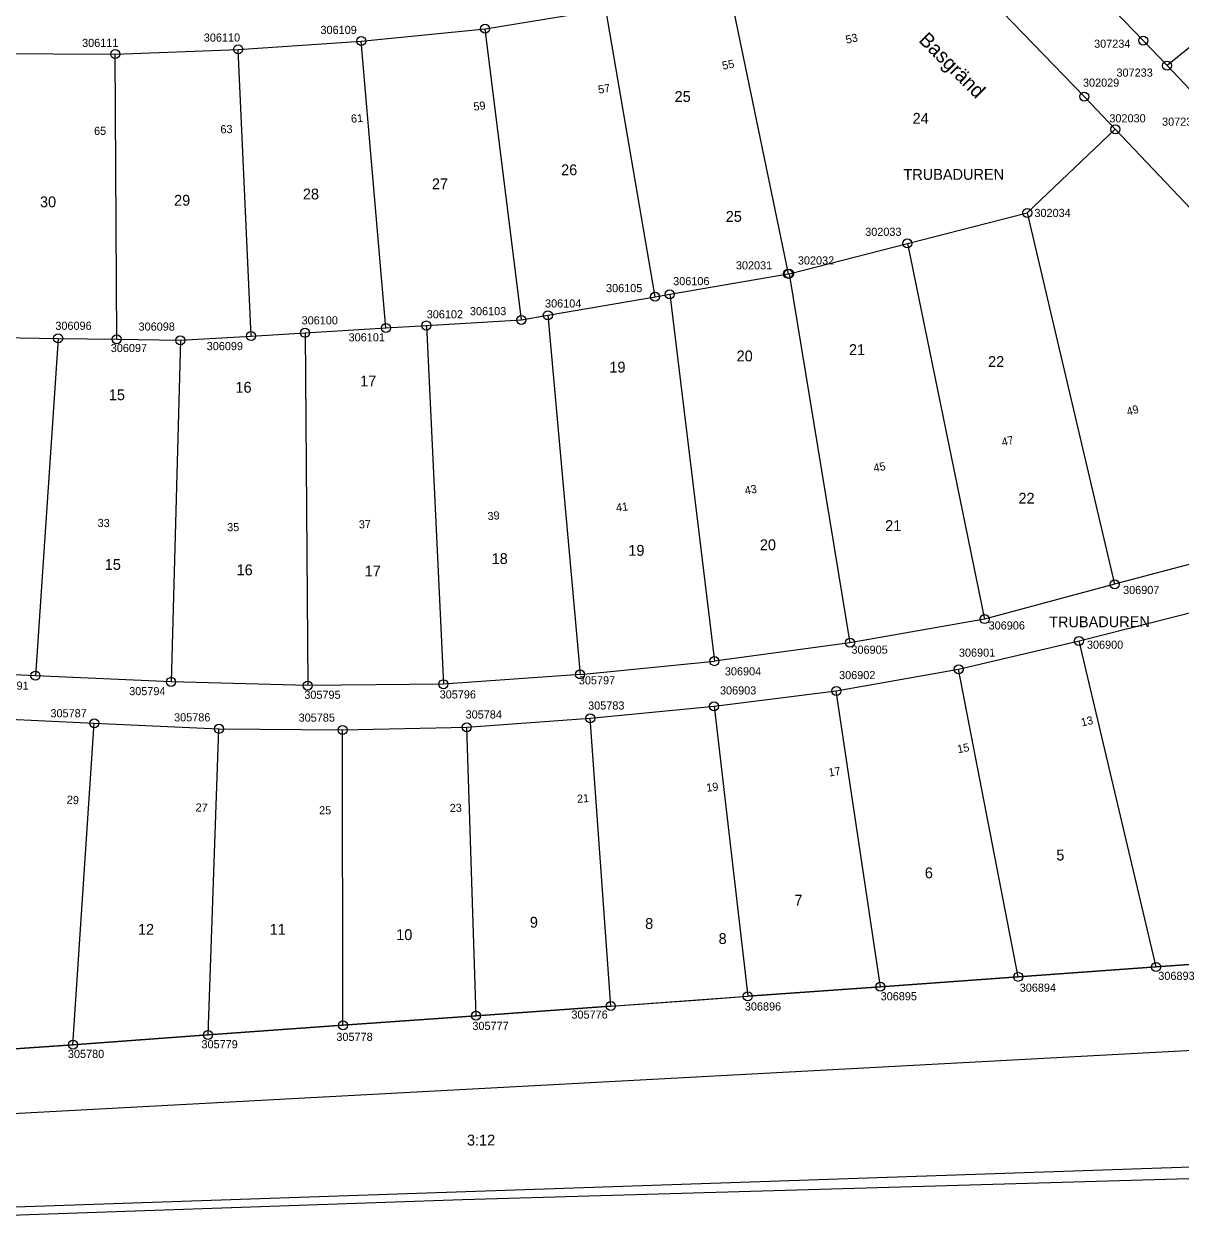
# Model space of a CAD drawing. Extents: x 141995 to 152570, y 6580184 to 6586000.
# Drawn here: x 142151.4 to 142279.5, y 6585356 to 6585489.3 of the extents above; entities that cross this region are included whole.
import ezdxf

# ---------------------------------------------------------------- set-up
doc = ezdxf.new("R2010")
doc.units = 0
for name, color, linetype in [('Level 10', 7, 'Continuous'), ('Level 13', 7, 'Continuous'), ('Level 43', 7, 'Continuous'), ('Level 5', 7, 'Continuous'), ('Level 51', 7, 'Continuous'), ('Level 53', 7, 'Continuous'), ('Level 54', 7, 'Continuous'), ('Level 58', 7, 'Continuous'), ('Level 59', 7, 'Continuous'), ('Level 6', 7, 'Continuous'), ('Level 7', 7, 'Continuous')]:
    doc.layers.add(name, color=color, linetype=linetype)

msp = doc.modelspace()

# ---------------------------------------------------------------- linework, layer by layer
at = {"layer": 'Level 10'}
for centre in [(142202.46, 6585488.79), (142188.75, 6585487.43), (142275.29, 6585487.49), (142175.13, 6585486.51), (142161.52, 6585485.99), (142277.92, 6585484.71), (142268.76, 6585481.29), (142272.2, 6585477.67), (142262.45, 6585468.41), (142249.19, 6585465.03), (142235.99, 6585461.67), (142236.09, 6585461.68), (142222.89, 6585459.41), (142221.27, 6585459.13), (142209.4, 6585457.08), (142191.48, 6585455.68), (142195.96, 6585455.95), (142206.47, 6585456.57), (142155.21, 6585454.53), (142161.69, 6585454.43), (142168.74, 6585454.31), (142176.56, 6585454.78), (142182.53, 6585455.14), (142272.12, 6585427.31), (142257.73, 6585423.45), (142242.83, 6585420.84), (142268.19, 6585421.04), (142227.84, 6585418.8), (142152.7, 6585417.19), (142212.97, 6585417.33), (142254.86, 6585417.91), (142167.71, 6585416.51), (142182.83, 6585416.1), (142197.85, 6585416.25), (142241.32, 6585415.5), (142227.79, 6585413.8), (142159.2, 6585411.93), (142200.43, 6585411.49), (142214.09, 6585412.48), (142173, 6585411.31), (142186.68, 6585411.19), (142276.72, 6585384.95), (142261.45, 6585383.86), (142246.2, 6585382.76), (142231.53, 6585381.71), (142201.46, 6585379.55), (142216.37, 6585380.62), (142186.73, 6585378.5), (142171.8, 6585377.43), (142156.85, 6585376.35)]:
    msp.add_circle(centre, 0.5, dxfattribs=at)
at = {"layer": 'Level 13'}
msp.add_lwpolyline([(142106.18, 6585355.96), (142199.95, 6585359.22), (142280.34, 6585361.53), (142298.3, 6585362.96), (142308.55, 6585364.2), (142315.26, 6585364.94), (142322.71, 6585365.48), (142328.56, 6585365.72), (142332.32, 6585365.37), (142336.72, 6585364.61), (142340.97, 6585363.81), (142343.67, 6585363.75), (142345.72, 6585364.6), (142347.07, 6585365.5), (142347.87, 6585367.45), (142347.76, 6585371.19)], dxfattribs=at)
at = {"layer": 'Level 5'}
for points in [[(142275.29, 6585487.49), (142265.8, 6585497.34)], [(142257.48, 6585492.99), (142268.76, 6585481.29)], [(142277.92, 6585484.71), (142275.29, 6585487.49)], [(142282.99, 6585479.38), (142277.92, 6585484.71)], [(142268.76, 6585481.29), (142272.2, 6585477.67)], [(142272.2, 6585477.67), (142305.7, 6585442.37)], [(142291.9, 6585386.04), (142276.72, 6585384.95)], [(142276.72, 6585384.95), (142261.45, 6585383.86)], [(142246.2, 6585382.76), (142231.53, 6585381.71)], [(142261.45, 6585383.86), (142246.2, 6585382.76)], [(142216.37, 6585380.62), (142231.53, 6585381.71)], [(142216.37, 6585380.62), (142201.46, 6585379.55)], [(142201.46, 6585379.55), (142186.73, 6585378.5)], [(142171.8, 6585377.43), (142156.85, 6585376.35)], [(142186.73, 6585378.5), (142171.8, 6585377.43)], [(142156.85, 6585376.35), (142142.94, 6585375.36)], [(142143.25, 6585368.36), (142295.25, 6585376.5)], [(142094.06, 6585356.49), (142340.21, 6585364.86)]]:
    msp.add_lwpolyline(points, dxfattribs=at)
at = {"layer": 'Level 6'}
for points in [[(142161.78, 6585599.85), (142163.75, 6585595.96), (142164.09, 6585595.28), (142167.01, 6585591.08), (142170.49, 6585587.33), (142174.96, 6585583.19), (142180.35, 6585578.22), (142185.73, 6585573.24), (142195.5, 6585564.2), (142205.48, 6585554.98), (142211, 6585549.86), (142216.54, 6585544.75), (142222.07, 6585539.63), (142227.15, 6585534.94), (142228.61, 6585533.59), (142240.56, 6585522.35), (142252.33, 6585510.92), (142263.91, 6585499.3), (142265.8, 6585497.34), (142275.29, 6585487.49), (142277.92, 6585484.71), (142282.99, 6585479.38)], [(142268.76, 6585481.29), (142257.48, 6585492.99), (142253.2, 6585497.29), (142246, 6585504.51), (142242.37, 6585508.05), (142234.34, 6585515.84), (142226.12, 6585523.57), (142222.49, 6585526.97), (142203, 6585545), (142172.41, 6585573.3), (142164.38, 6585580.72), (142159.99, 6585585.41), (142156.32, 6585590.67), (142155.3, 6585592.5), (142154.06, 6585594.1), (142152.36, 6585595.2), (142150.39, 6585595.67)], [(142303.68, 6585444.5), (142272.2, 6585477.67), (142268.76, 6585481.29)], [(142142.94, 6585375.36), (142156.85, 6585376.35), (142171.8, 6585377.43), (142186.73, 6585378.5), (142201.46, 6585379.55), (142216.37, 6585380.62), (142226.24, 6585381.33), (142231.53, 6585381.71), (142246.2, 6585382.76), (142261.45, 6585383.86), (142276.72, 6585384.95), (142291.9, 6585386.04)]]:
    msp.add_lwpolyline(points, dxfattribs=at)
at = {"layer": 'Level 7'}
for points in [[(142306.32, 6585507.63), (142277.92, 6585484.71)], [(142229.37, 6585493.73), (142235.99, 6585461.67)], [(142202.46, 6585488.79), (142215.83, 6585490.98)], [(142221.27, 6585459.13), (142215.83, 6585490.98)], [(142188.75, 6585487.43), (142202.46, 6585488.79)], [(142206.47, 6585456.57), (142202.46, 6585488.79)], [(142175.13, 6585486.51), (142188.75, 6585487.43)], [(142191.48, 6585455.68), (142188.75, 6585487.43)], [(142147.81, 6585486.06), (142161.52, 6585485.99)], [(142161.52, 6585485.99), (142175.13, 6585486.51)], [(142161.69, 6585454.43), (142161.52, 6585485.99)], [(142176.56, 6585454.78), (142175.13, 6585486.51)], [(142262.45, 6585468.41), (142272.2, 6585477.67)], [(142249.19, 6585465.03), (142262.45, 6585468.41)], [(142262.45, 6585468.41), (142272.12, 6585427.31)], [(142236.09, 6585461.68), (142249.19, 6585465.03)], [(142249.19, 6585465.03), (142257.73, 6585423.45)], [(142222.89, 6585459.41), (142235.99, 6585461.67)], [(142235.99, 6585461.67), (142236.09, 6585461.68)], [(142236.09, 6585461.68), (142242.83, 6585420.84)], [(142209.4, 6585457.08), (142221.27, 6585459.13)], [(142221.27, 6585459.13), (142222.89, 6585459.41)], [(142222.89, 6585459.41), (142227.84, 6585418.8)], [(142191.48, 6585455.68), (142195.96, 6585455.95)], [(142195.96, 6585455.95), (142206.47, 6585456.57)], [(142195.96, 6585455.95), (142197.85, 6585416.25)], [(142206.47, 6585456.57), (142209.4, 6585457.08)], [(142209.4, 6585457.08), (142212.97, 6585417.33)], [(142146.73, 6585454.67), (142155.21, 6585454.53)], [(142168.74, 6585454.31), (142176.56, 6585454.78)], [(142176.56, 6585454.78), (142182.53, 6585455.14)], [(142182.53, 6585455.14), (142191.48, 6585455.68)], [(142182.53, 6585455.14), (142182.83, 6585416.1)], [(142155.21, 6585454.53), (142152.7, 6585417.19)], [(142155.21, 6585454.53), (142161.69, 6585454.43)], [(142161.69, 6585454.43), (142168.74, 6585454.31)], [(142168.74, 6585454.31), (142167.71, 6585416.51)], [(142285.81, 6585430.94), (142272.12, 6585427.31)], [(142272.12, 6585427.31), (142257.73, 6585423.45)], [(142268.19, 6585421.04), (142281.44, 6585424.4)], [(142257.73, 6585423.45), (142242.83, 6585420.84)], [(142242.83, 6585420.84), (142227.84, 6585418.8)], [(142254.86, 6585417.91), (142268.19, 6585421.04)], [(142276.72, 6585384.95), (142268.19, 6585421.04)], [(142212.97, 6585417.33), (142227.84, 6585418.8)], [(142152.7, 6585417.19), (142134.22, 6585418.04)], [(142212.97, 6585417.33), (142197.85, 6585416.25)], [(142241.32, 6585415.5), (142254.86, 6585417.91)], [(142261.45, 6585383.86), (142254.86, 6585417.91)], [(142167.71, 6585416.51), (142152.7, 6585417.19)], [(142182.83, 6585416.1), (142167.71, 6585416.51)], [(142197.85, 6585416.25), (142182.83, 6585416.1)], [(142227.79, 6585413.8), (142241.32, 6585415.5)], [(142246.2, 6585382.76), (142241.32, 6585415.5)], [(142214.09, 6585412.48), (142227.79, 6585413.8)], [(142227.79, 6585413.8), (142231.53, 6585381.71)], [(142143.64, 6585412.69), (142159.2, 6585411.93)], [(142156.85, 6585376.35), (142159.2, 6585411.93)], [(142159.2, 6585411.93), (142173, 6585411.31)], [(142200.43, 6585411.49), (142214.09, 6585412.48)], [(142216.37, 6585380.62), (142214.09, 6585412.48)], [(142171.8, 6585377.43), (142173, 6585411.31)], [(142173, 6585411.31), (142186.68, 6585411.19)], [(142186.68, 6585411.19), (142200.43, 6585411.49)], [(142186.73, 6585378.5), (142186.68, 6585411.19)], [(142201.46, 6585379.55), (142200.43, 6585411.49)]]:
    msp.add_lwpolyline(points, dxfattribs=at)

# ---------------------------------------------------------------- texts
at = {"layer": 'Level 43'}
msp.add_text('Basgränd', height=1.6, rotation=315.0514, dxfattribs=at).set_placement((142250.35, 6585487.44))
at = {"layer": 'Level 51'}
for s, rotation, p in [('25', 0.0527, (142223.43, 6585480.69)), ('24', 0.0527, (142249.77, 6585478.28)), ('26', 0.0527, (142210.87, 6585472.58)), ('27', 0.0527, (142196.57, 6585471.03)), ('28', 0.0527, (142182.29, 6585469.9)), ('30', 0.0527, (142153.2, 6585469.04)), ('29', 0.0527, (142168.04, 6585469.21)), ('22', 0.0527, (142261.48, 6585436.23)), ('21', 0.0527, (142246.73, 6585433.2)), ('20', 0.0527, (142232.86, 6585431.08)), ('18', 0.0527, (142203.18, 6585429.55)), ('19', 0.0527, (142218.31, 6585430.46)), ('15', 0.0527, (142160.37, 6585428.9)), ('16', 0.0527, (142174.96, 6585428.31)), ('17', 0.0527, (142189.13, 6585428.18)), ('5', 0.0526, (142265.67, 6585396.74)), ('6', 0.0526, (142251.12, 6585394.77)), ('7', 0.0526, (142236.69, 6585391.74)), ('12', 0.0526, (142164.04, 6585388.51)), ('11', 0.0526, (142178.61, 6585388.52)), ('9', 0.0526, (142207.41, 6585389.3)), ('8', 0.0526, (142220.17, 6585389.16)), ('10', 0.0526, (142192.62, 6585387.93)), ('3:12', 0.0526, (142200.45, 6585365.19))]:
    msp.add_text(s, height=1.2, rotation=rotation, dxfattribs=at).set_placement(p)
at = {"layer": 'Level 53'}
for s, rotation, p in [('306110', 0.0527, (142171.33, 6585487.37)), ('306109', 0.0527, (142184.24, 6585488.22)), ('306111', 0.0527, (142157.86, 6585486.78)), ('307234', 0.0527, (142269.85, 6585486.69)), ('307233', 0.0527, (142272.33, 6585483.49)), ('302029', 0.0527, (142268.62, 6585482.38)), ('302030', 0.0527, (142271.54, 6585478.43)), ('307232', 0.0527, (142277.37, 6585478.06)), ('302034', 0.0527, (142263.25, 6585467.96)), ('302033', 0.0527, (142244.52, 6585465.87)), ('302031', 0.0527, (142230.21, 6585462.16)), ('302032', 0.0527, (142237.07, 6585462.7)), ('306106', 0.0527, (142223.27, 6585460.41)), ('306105', 0.0527, (142215.84, 6585459.64)), ('306104', 0.0527, (142209.09, 6585457.94)), ('306102', 0.0527, (142196, 6585456.74)), ('306103', 0.0527, (142200.78, 6585457.09)), ('306096', 0.0527, (142154.9, 6585455.47)), ('306098', 0.0527, (142164.11, 6585455.38)), ('306100', 0.0527, (142182.15, 6585456.07)), ('306101', 0.0527, (142187.35, 6585454.19)), ('306097', 0.0527, (142161.03, 6585453.01)), ('306099', 0.0527, (142171.65, 6585453.22)), ('306907', 0.0527, (142273.06, 6585426.23)), ('306906', 0.0527, (142258.18, 6585422.3)), ('306905', 0.0527, (142243, 6585419.62)), ('306901', 0.0527, (142254.89, 6585419.29)), ('306900', 0.0527, (142269.06, 6585420.17)), ('306904', 0.0527, (142228.99, 6585417.22)), ('306902', 0.0527, (142241.63, 6585416.81)), ('305791', 0.0527, (142147.93, 6585415.64)), ('305794', 0.0527, (142163.07, 6585415.03)), ('305797', 0.0527, (142212.83, 6585416.23)), ('306903', 0.0527, (142228.45, 6585415.11)), ('305795', 0.0527, (142182.45, 6585414.63)), ('305796', 0.0527, (142197.43, 6585414.67)), ('305787', 0.0527, (142154.36, 6585412.58)), ('305784', 0.0527, (142200.3, 6585412.45)), ('305783', 0.0527, (142213.86, 6585413.44)), ('305786', 0.0527, (142168.04, 6585412.13)), ('305785', 0.0527, (142181.82, 6585412.1)), ('306893', 0.0526, (142276.96, 6585383.52)), ('306894', 0.0526, (142261.62, 6585382.21)), ('306895', 0.0526, (142246.23, 6585381.26)), ('305776', 0.0526, (142212.01, 6585379.23)), ('306896', 0.0526, (142231.2, 6585380.13)), ('305777', 0.0526, (142201.05, 6585377.98)), ('305778', 0.0526, (142186, 6585376.77)), ('305779', 0.0526, (142171.07, 6585375.95)), ('305780', 0.0526, (142156.29, 6585374.88))]:
    msp.add_text(s, height=0.9, rotation=rotation, dxfattribs=at).set_placement(p)
at = {"layer": 'Level 54'}
for s, rotation, p in [('53', 13.1716, (142242.47, 6585487.12)), ('55', 11.5986, (142228.79, 6585484.25)), ('57', 9.4007, (142215.04, 6585481.6)), ('59', 7.1257, (142201.22, 6585479.72)), ('61', 4.8487, (142187.65, 6585478.38)), ('65', 0.3157, (142159.18, 6585477.04)), ('63', 2.5647, (142173.19, 6585477.2)), ('49', 16.0216, (142273.59, 6585445.95)), ('47', 13.3076, (142259.73, 6585442.58)), ('45', 11.6436, (142245.53, 6585439.71)), ('43', 9.3137, (142231.26, 6585437.23)), ('41', 7.1637, (142217, 6585435.33)), ('33', 358.7657, (142159.57, 6585433.66)), ('39', 5.0157, (142202.77, 6585434.39)), ('35', 0.5747, (142173.92, 6585433.18)), ('37', 2.8447, (142188.51, 6585433.48)), ('13', 13.2556, (142268.51, 6585411.56)), ('15', 11.0346, (142254.8, 6585408.6)), ('17', 8.5967, (142240.53, 6585406.02)), ('19', 6.6864, (142226.99, 6585404.34)), ('29', 356.0957, (142156.14, 6585403.04)), ('21', 4.2165, (142212.66, 6585403.11)), ('27', 357.8936, (142170.4, 6585402.17)), ('25', 0.1876, (142184.09, 6585401.84)), ('23', 2.0145, (142198.56, 6585402.09))]:
    msp.add_text(s, height=0.9, rotation=rotation, dxfattribs=at).set_placement(p)
at = {"layer": 'Level 58'}
for rotation, p in [(0.0527, (142248.75, 6585472.07)), (0.2627, (142264.88, 6585422.53))]:
    msp.add_text('TRUBADUREN', height=1.2, rotation=rotation, dxfattribs=at).set_placement(p)
at = {"layer": 'Level 59'}
for s, rotation, p in [('25', 0.0527, (142229.09, 6585467.42)), ('21', 0.0527, (142242.73, 6585452.68)), ('19', 0.0527, (142216.21, 6585450.74)), ('20', 0.0527, (142230.29, 6585451.98)), ('22', 0.0527, (142258.12, 6585451.36)), ('16', 0.0527, (142174.83, 6585448.51)), ('17', 0.0527, (142188.63, 6585449.21)), ('15', 0.0527, (142160.82, 6585447.68)), ('8', 0.0526, (142228.3, 6585387.49))]:
    msp.add_text(s, height=1.2, rotation=rotation, dxfattribs=at).set_placement(p)

doc.saveas('drawing.dxf')
